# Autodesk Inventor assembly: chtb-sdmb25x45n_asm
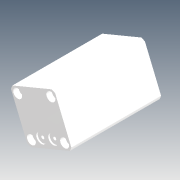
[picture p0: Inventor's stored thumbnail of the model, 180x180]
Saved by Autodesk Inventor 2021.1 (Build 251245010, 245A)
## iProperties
Company: Microsoft
Created: 2018-05
Part Number: chtb-sdmb25x45n_asm
Description: STEP AP214
Document SubType Name: Assembly
Designer: user
Title: chtb-sdmb25x45n_asm.STEP
Author: Windows
Revision Number: ÈÎºÎ
Sending System: SolidWorks 2015
Preprocessor: SwSTEP 2.0
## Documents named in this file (4)
- D:\Vault_2016\Projekty\Clamptek\Hydraulic\CHTB\CHTB-25\Inventor\chtb-sdmb25x45n\chtb-sdmb25x45n_asm.iam
- D:\Vault_2016\Projekty\Clamptek\Hydraulic\CHTB\CHTB-25\Inventor\chtb-sdmb25x45n\CHTB-25QG.ipt
- D:\Vault_2016\Projekty\Clamptek\Hydraulic\CHTB\CHTB-25\Inventor\chtb-sdmb25x45n\CHTB-SDMB25X45NBT.ipt
- D:\Vault_2016\Projekty\Clamptek\Hydraulic\CHTB\CHTB-25\Inventor\chtb-sdmb25x45n\CHTB-SDMB25X45NHSG.ipt
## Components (3 placed, 3 different names)
1. CHTB-25QG_1
2. CHTB-SDMB25X45NBT_2
3. CHTB-SDMB25X45NHSG_3
